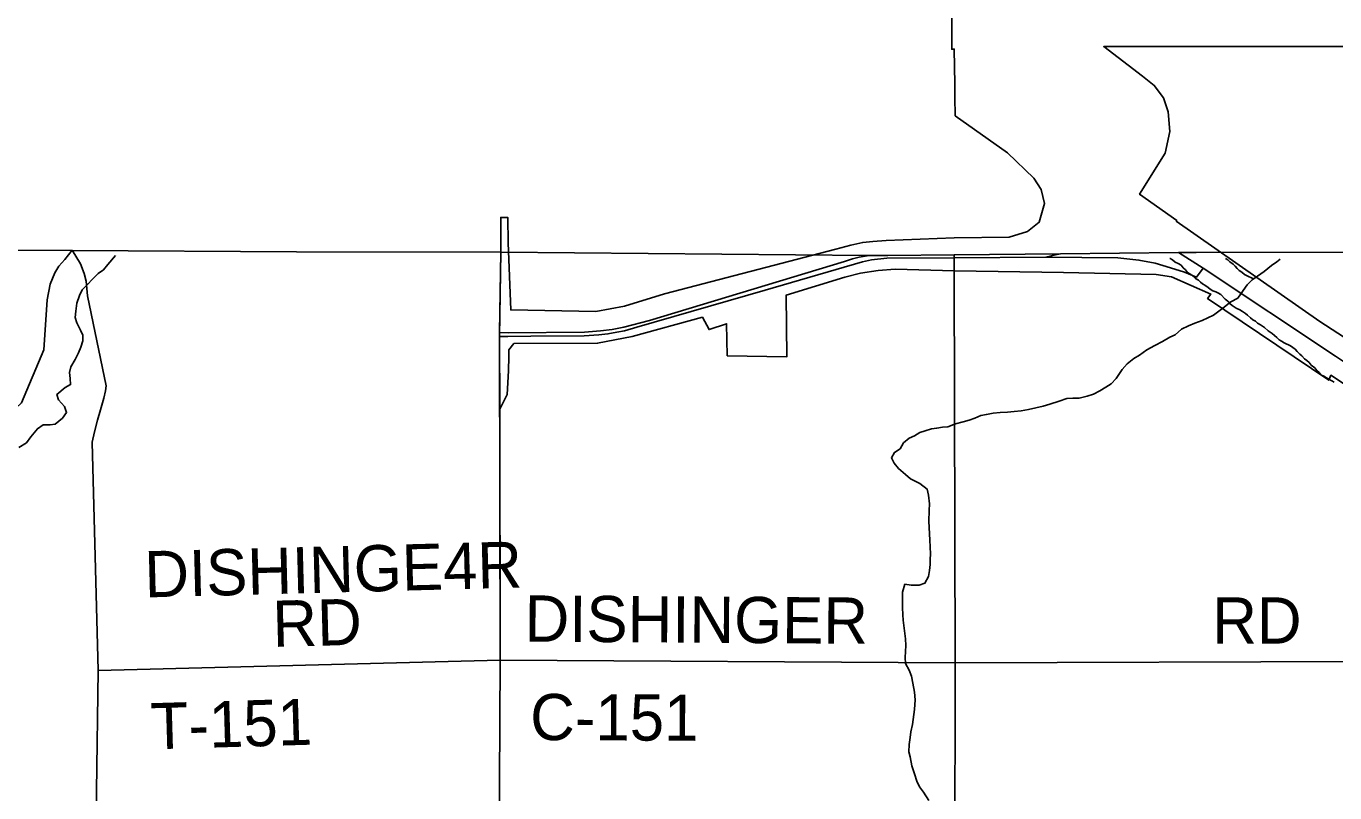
# Model space of a CAD drawing. Extents: x 1588073 to 2013523, y 1090242 to 1357120.
# Drawn here: x 1746125 to 1754621, y 1257155 to 1262131 of the extents above; entities that cross this region are included whole.
import ezdxf

# ---------------------------------------------------------------- set-up
doc = ezdxf.new("R2010")
doc.units = 0
for name, color, linetype in [('GM_X_Adjacent_County', 7, 'Continuous'), ('GM_X_City_Street', 7, 'Continuous'), ('GM_X_Corporation', 7, 'Continuous'), ('GM_X_County', 7, 'Continuous'), ('GM_X_County_Road', 7, 'Continuous'), ('GM_X_County_Road_Text', 7, 'Continuous'), ('GM_X_Interchange_Ramps', 7, 'Continuous'), ('GM_X_Interstate_Route', 7, 'Continuous'), ('GM_X_Minor_River', 7, 'Continuous'), ('GM_X_State_Route', 7, 'Continuous'), ('GM_X_Township', 7, 'Continuous'), ('GM_X_Township_Road', 7, 'Continuous'), ('GM_X_Township_Road_Text', 7, 'Continuous')]:
    doc.layers.add(name, color=color, linetype=linetype)

msp = doc.modelspace()

# ---------------------------------------------------------------- linework, layer by layer
at = {"layer": 'GM_X_Adjacent_County'}
msp.add_lwpolyline([(1738897.5, 1260682), (1743909.5, 1260685.3), (1746424.3, 1260675.9), (1747879.2, 1260667.3), (1749206.8, 1260663.9), (1751597.5, 1260643.2), (1751719.7, 1260643.4), (1752150.2, 1260647), (1752840, 1260654.1), (1753605.7, 1260661.4), (1753720.2, 1260661.7), (1754797.2, 1260664.8)], dxfattribs=at)
at = {"layer": 'GM_X_City_Street'}
msp.add_lwpolyline([(1752150.1, 1260541), (1752149.9, 1260627.4), (1752150.2, 1260647)], dxfattribs=at)
at = {"layer": 'GM_X_Corporation'}
for points in [[(1754791.4, 1259736.3), (1754595.1, 1259864.7), (1754581.4, 1259832.7), (1753794.9, 1260363.9), (1753815.7, 1260391.7), (1753560.3, 1260504.8), (1753460.5, 1260519.5), (1752859.8, 1260532.5), (1752151.5, 1260543.8), (1751766.9, 1260554.2), (1751655.8, 1260544.7), (1751542.1, 1260527.3), (1751438.8, 1260501.3), (1751059.4, 1260385.8), (1751064.1, 1259984.9), (1750676.1, 1259991.8), (1750671.8, 1260199.3), (1750558, 1260161.1), (1750515.5, 1260241.8), (1750059.8, 1260116.8), (1749835, 1260072.6), (1749291.6, 1260070.8), (1749259.4, 1260030.9), (1749257.7, 1259987.5), (1749256.8, 1259893.7), (1749247.3, 1259739.2), (1749199.5, 1259644.6), (1749198.5, 1260116.5), (1749206.8, 1260663.9), (1749205.8, 1260794.6), (1749205.8, 1260889.4), (1749251.6, 1260889.4), (1749254.2, 1260724.5), (1749270.7, 1260288.7), (1749822.8, 1260279.2), (1750009.4, 1260313.9), (1750269, 1260392.9), (1751380.6, 1260684.4), (1751479.6, 1260710.5), (1751556, 1260727.8), (1751621.9, 1260733.1), (1751708.7, 1260740), (1752149.4, 1260758), (1752505.6, 1260762.1), (1752625.4, 1260797.3), (1752702.2, 1260858.1), (1752736.5, 1260980.5), (1752714.4, 1261069.9), (1752667.5, 1261143.6), (1752496.1, 1261309.9), (1752155.8, 1261549), (1752154.5, 1261670.8), (1752154.2, 1261754.9), (1752150.3, 1261981.8), (1752134.3, 1261981.3), (1752134, 1262112), (1752131.5, 1262303.7)], [(1754784.9, 1261998.4), (1753120.4, 1261998.5), (1753371.3, 1261806.4), (1753448.5, 1261746.7), (1753509.2, 1261665.7), (1753538.8, 1261574.9), (1753549.2, 1261446.4), (1753519.7, 1261307.5), (1753353.1, 1261040.2), (1753594.2, 1260870.5), (1753591.4, 1260866.3), (1754522.7, 1260214.6), (1754793.2, 1260039.3)]]:
    msp.add_lwpolyline(points, dxfattribs=at)
at = {"layer": 'GM_X_County'}
msp.add_lwpolyline([(1738897.5, 1260682), (1743909.5, 1260685.3), (1746424.3, 1260675.9), (1747879.2, 1260667.3), (1749206.8, 1260663.9), (1751597.5, 1260643.2), (1751719.7, 1260643.4), (1752150.2, 1260647), (1752840, 1260654.1), (1753605.7, 1260661.4), (1753720.2, 1260661.7), (1754797.2, 1260664.8)], dxfattribs=at)
at = {"layer": 'GM_X_County_Road'}
for points in [[(1749203, 1258015.3), (1752155.7, 1257998.2)], [(1752155.7, 1257998.2), (1754803.4, 1258006.5)]]:
    msp.add_lwpolyline(points, dxfattribs=at)
at = {"layer": 'GM_X_Interchange_Ramps'}
for points in [[(1751597.5, 1260643.2), (1751532.1, 1260630.6), (1751490.2, 1260620.7), (1751437.4, 1260604.5), (1750170.7, 1260219.5), (1750004.7, 1260176.7), (1749929.1, 1260161.6), (1749853.7, 1260154.1), (1749750.5, 1260144), (1749254.7, 1260141.5), (1749198.5, 1260141.7)], [(1749198.5, 1260116.5), (1749252.2, 1260116.3), (1749400.7, 1260118.8), (1749748, 1260121.3), (1749843.6, 1260126.4), (1749901.5, 1260133.9), (1749959.4, 1260144), (1750009.7, 1260154.1), (1750090.2, 1260176.7), (1750923.2, 1260418.4), (1751554.9, 1260602.2), (1751612.8, 1260614.8), (1751712.4, 1260625.7), (1752149.9, 1260627.4), (1752744, 1260632.3), (1753211.4, 1260627.7), (1753348.8, 1260613), (1753455.3, 1260592), (1753555, 1260563.3), (1753644.8, 1260534.1), (1753722.6, 1260501.3), (1753765.8, 1260560.3)], [(1752744, 1260632.3), (1752772.5, 1260639.1), (1752795.5, 1260644.1), (1752840, 1260654.1)]]:
    msp.add_lwpolyline(points, dxfattribs=at)
at = {"layer": 'GM_X_Interstate_Route'}
msp.add_lwpolyline([(1753605.7, 1260661.4), (1753765.8, 1260560.3), (1754626.2, 1259989.1), (1754702.6, 1259937.7)], dxfattribs=at)
at = {"layer": 'GM_X_Minor_River'}
for points in [[(1746078.2, 1259397), (1746126.5, 1259426.5), (1746155, 1259466.3), (1746197.5, 1259518), (1746235.8, 1259543.6), (1746279.9, 1259543.2), (1746313.9, 1259546.9), (1746360.4, 1259586.5), (1746386.8, 1259622.3), (1746373.2, 1259662.5), (1746335.6, 1259705), (1746323.9, 1259739.2), (1746378.5, 1259786.7), (1746412.7, 1259804.4), (1746411.1, 1259844.5), (1746405.5, 1259882.6), (1746413.9, 1259920.6), (1746442.4, 1259968.4), (1746464.8, 1260010.3), (1746479.3, 1260048.2), (1746491.7, 1260088.2), (1746492.1, 1260124.3), (1746478.4, 1260158.5), (1746452.9, 1260204.8), (1746443.2, 1260239), (1746447.6, 1260281.1), (1746454.2, 1260333.1), (1746470.7, 1260383), (1746489.1, 1260418.9), (1746523.5, 1260454.6), (1746555.9, 1260488.4), (1746592.3, 1260526.1), (1746626.6, 1260549.8), (1746654.9, 1260583.6), (1746703.8, 1260643)], [(1753548.9, 1260623.3), (1753550.8, 1260622.5), (1753566.7, 1260614.3), (1753584.5, 1260600), (1753604.3, 1260589.7), (1753622.2, 1260579.4), (1753636, 1260563.1), (1753651.8, 1260548.9), (1753663.6, 1260532.7), (1753679.4, 1260522.4), (1753693.3, 1260514.2), (1753717.1, 1260493.8), (1753734.9, 1260481.5), (1753748.7, 1260469.3), (1753762.6, 1260459.1), (1753776.5, 1260448.8), (1753798.3, 1260434.5), (1753812.1, 1260424.3), (1753828, 1260414), (1753847.9, 1260405.7), (1753861.8, 1260399.5), (1753879.7, 1260389.2), (1753909.3, 1260358.7), (1753925.1, 1260346.4), (1753940.9, 1260328.2), (1753954.7, 1260317.9), (1753980.5, 1260299.5), (1754004.4, 1260289.1), (1754022.2, 1260278.9), (1754040.1, 1260266.6), (1754053.9, 1260254.3), (1754073.7, 1260238), (1754087.5, 1260225.8), (1754105.4, 1260215.5), (1754119.2, 1260203.3), (1754139.1, 1260193), (1754164.9, 1260174.6), (1754188.6, 1260154.2), (1754214.3, 1260135.8), (1754244, 1260109.3), (1754259.8, 1260095), (1754273.7, 1260086.8), (1754291.6, 1260076.5), (1754305.4, 1260068.3), (1754319.4, 1260062.1), (1754333.3, 1260055.8), (1754349.2, 1260045.6), (1754363, 1260035.3), (1754376.8, 1260019.1), (1754392.6, 1260002.8), (1754406.4, 1259990.6), (1754424.2, 1259972.3), (1754438, 1259960.1), (1754453.8, 1259947.8), (1754467.6, 1259931.6), (1754491.4, 1259913.2), (1754503.1, 1259895), (1754518.9, 1259882.8), (1754530.7, 1259868.6), (1754548.6, 1259858.3), (1754584.4, 1259837.7), (1754602.2, 1259829.4), (1754616.1, 1259821.2)], [(1753911.3, 1260622.6), (1753927.1, 1260614.9), (1753938.9, 1260600.7), (1753960.7, 1260586.4), (1753974.6, 1260574.2), (1753986.3, 1260558), (1754000.2, 1260545.7), (1754018, 1260533.4), (1754033.8, 1260519.2), (1754047.7, 1260513), (1754092.3, 1260491.2)], [(1754266.3, 1260618.3), (1754244.8, 1260601.7), (1754208.6, 1260578), (1754162.1, 1260538.4), (1754117.8, 1260508.8), (1754083.5, 1260485.1), (1754051.1, 1260451.4), (1754026.7, 1260415.6), (1753990.2, 1260365.8), (1753945.9, 1260342.2), (1753893.4, 1260300.7), (1753832.9, 1260255.2), (1753760.5, 1260219.8), (1753712.3, 1260202.3), (1753670.1, 1260186.7), (1753625.8, 1260165.1), (1753583.4, 1260127.5), (1753549.2, 1260111.8), (1753502.9, 1260084.2), (1753452.6, 1260058.7), (1753400.2, 1260029.1), (1753351.9, 1259995.6), (1753315.6, 1259973.9), (1753273.2, 1259938.2), (1753240.8, 1259902.5), (1753200.2, 1259844.8), (1753167.8, 1259809.1), (1753133.5, 1259787.4), (1753095.3, 1259763.7), (1753055, 1259742.1), (1753012.8, 1259728.5), (1752960.7, 1259717), (1752920.6, 1259717.4), (1752880.6, 1259713.8), (1752830.4, 1259696.3), (1752770.1, 1259676.9), (1752728, 1259665.3), (1752631.6, 1259642.2), (1752585.5, 1259634.7), (1752539.4, 1259629.1), (1752495.4, 1259625.6), (1752447.3, 1259624.1), (1752403.2, 1259618.5), (1752359.1, 1259610.9), (1752323, 1259603.3), (1752282.8, 1259585.7), (1752246.7, 1259574), (1752208.5, 1259562.4), (1752158.3, 1259548.9), (1752108.1, 1259531.3), (1752074, 1259527.7), (1752036, 1259522.1), (1752001.9, 1259516.4), (1751961.7, 1259504.8), (1751925.6, 1259493.1), (1751891.3, 1259471.4), (1751857.1, 1259455.8), (1751820.8, 1259426.1), (1751798.4, 1259388.2), (1751762.1, 1259364.5), (1751741.7, 1259328.7), (1751759.4, 1259294.4), (1751789, 1259260.1), (1751832.7, 1259221.5), (1751866.4, 1259193.1), (1751926.1, 1259162.4), (1751973.8, 1259125.9), (1751983.4, 1259087.7), (1751988.8, 1259029.5), (1751986.4, 1258987.4), (1751985.6, 1258917.3), (1751987.2, 1258877.2), (1751988.8, 1258835.1), (1751992.4, 1258795), (1751993.9, 1258750.8), (1751995.4, 1258704.7), (1751993.1, 1258670.7), (1751992.7, 1258636.6), (1751988.3, 1258598.6), (1751983.9, 1258558.5), (1751959.4, 1258514.7), (1751923.3, 1258503.1), (1751871.3, 1258503.6), (1751829.3, 1258508), (1751814.7, 1258456.1), (1751813.7, 1258357.9), (1751815.2, 1258309.8), (1751818.8, 1258275.6), (1751824.3, 1258223.5), (1751833.6, 1258155.2), (1751835.2, 1258111.1), (1751832.8, 1258073.1), (1751830.3, 1258033), (1751833.9, 1257994.9), (1751857.5, 1257950.5), (1751873.1, 1257912.3)], [(1751873.1, 1257912.3), (1751880.6, 1257866.1), (1751892, 1257807.9), (1751895.5, 1257757.7), (1751892.9, 1257695.6), (1751877.9, 1257597.6), (1751867.4, 1257551.6), (1751863, 1257513.6), (1751856.5, 1257467.5), (1751856, 1257421.4), (1751863.7, 1257387.3), (1751875.1, 1257329), (1751892.5, 1257278.7), (1751908.1, 1257230.5), (1751923.7, 1257194.2), (1751949.4, 1257159.9), (1751984.8, 1257105.4)]]:
    msp.add_lwpolyline(points, dxfattribs=at)
at = {"layer": 'GM_X_State_Route'}
for points in [[(1749199.5, 1259643.7), (1749198.5, 1260116.5), (1749198.5, 1260141.7), (1749206.8, 1260663.9)], [(1749132.8, 1248594.3), (1749179.9, 1254041.7), (1749203, 1258015.3), (1749199.5, 1259643.7)]]:
    msp.add_lwpolyline(points, dxfattribs=at)
at = {"layer": 'GM_X_Township'}
for points in [[(1738897.5, 1260682), (1743909.5, 1260685.3), (1746424.3, 1260675.9), (1747879.2, 1260667.3), (1749206.8, 1260663.9), (1749198.5, 1260141.7), (1749198.5, 1260116.5), (1749203, 1258015.3), (1749179.9, 1254041.7), (1749132.8, 1248594.3), (1749049.4, 1246137.3)], [(1754797.2, 1260664.8), (1753720.2, 1260661.7), (1753605.7, 1260661.4), (1752840, 1260654.1), (1752150.2, 1260647), (1751719.7, 1260643.4), (1751597.5, 1260643.2), (1749206.8, 1260663.9), (1749198.5, 1260141.7), (1749198.5, 1260116.5), (1749203, 1258015.3), (1749179.9, 1254041.7), (1749132.8, 1248594.3), (1749049.4, 1246137.3)]]:
    msp.add_lwpolyline(points, dxfattribs=at)
at = {"layer": 'GM_X_Township_Road'}
for points in [[(1743875.2, 1258036.9), (1744245.7, 1258263.4), (1744639.5, 1258437.3), (1745582.4, 1259207.8), (1746095.5, 1259686.6), (1746239.6, 1260031.1), (1746261.2, 1260355.4), (1746279.6, 1260457), (1746310, 1260529.9), (1746337.2, 1260572.3), (1746376.4, 1260617.1), (1746424.4, 1260676)], [(1746548.6, 1254798.3), (1746548.9, 1254815.5), (1746593.3, 1257947.8), (1746554.2, 1259430.3), (1746569.3, 1259498.2), (1746588.6, 1259574.1), (1746607.8, 1259640), (1746629.1, 1259715.8), (1746639.9, 1259763.8), (1746644.5, 1259795.8), (1746522.9, 1260380.2), (1746514.1, 1260476.3), (1746500.4, 1260525.1), (1746478.2, 1260587.4), (1746424.4, 1260676)], [(1752096.5, 1250110.1), (1752110.9, 1250112.3), (1752130.4, 1250119.4), (1752147.3, 1250129.8), (1752163.6, 1250143.5), (1752172, 1250167.4), (1752177.4, 1250251.6), (1752148.9, 1254025.9), (1752155.7, 1257998.2), (1752150.1, 1260541)], [(1746593.3, 1257947.8), (1749203, 1258015.3)]]:
    msp.add_lwpolyline(points, dxfattribs=at)

# ---------------------------------------------------------------- texts
at = {"layer": 'GM_X_County_Road_Text'}
for s, rotation, p in [('DISHINGER', 359.61691, (1749360.1, 1258136.6)), ('RD', 0.00001, (1753825.3, 1258123.3)), ('C-151', 359.72469, (1749396.4, 1257497.3))]:
    msp.add_text(s, height=300, rotation=rotation, dxfattribs=at).set_placement(p)
at = {"layer": 'GM_X_Township_Road_Text'}
for s, rotation, p in [('DISHINGE4R', 1.51669, (1746896.1, 1258422.6)), ('RD', 1.48068, (1747727.7, 1258101.4)), ('T-151', 1.68484, (1746937, 1257436.5))]:
    msp.add_text(s, height=300, rotation=rotation, dxfattribs=at).set_placement(p)

doc.saveas('drawing.dxf')
